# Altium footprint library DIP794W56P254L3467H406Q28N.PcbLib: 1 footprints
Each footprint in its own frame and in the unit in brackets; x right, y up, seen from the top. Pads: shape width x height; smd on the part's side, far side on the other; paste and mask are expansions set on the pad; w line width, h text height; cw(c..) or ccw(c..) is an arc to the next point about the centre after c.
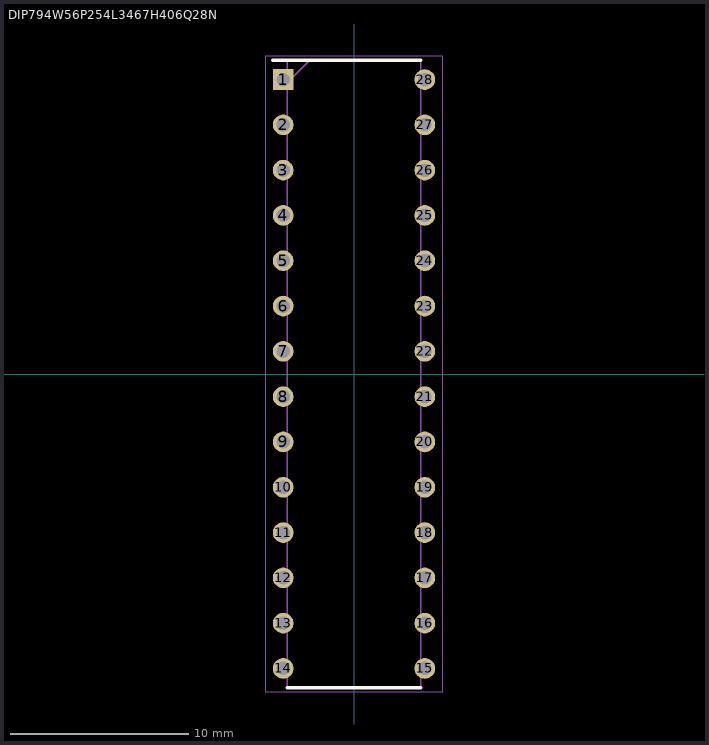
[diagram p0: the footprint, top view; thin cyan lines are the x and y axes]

## DIP794W56P254L3467H406Q28N [mm]
pads (28):
  rect 1.16x1.16 / inner round 1.16 / far side rect 1.16x1.16 hole 0.76: 1(-3.97,16.51)
  round 1.16 hole 0.76: 2(-3.97,13.97) 3(-3.97,11.43) 4(-3.97,8.89) 5(-3.97,6.35) 6(-3.97,3.81) 7(-3.97,1.27) 8(-3.97,-1.27) 9(-3.97,-3.81) 10(-3.97,-6.35) 11(-3.97,-8.89) 12(-3.97,-11.43) 13(-3.97,-13.97) 14(-3.97,-16.51) 15(3.97,-16.51) 16(3.97,-13.97) 17(3.97,-11.43) 18(3.97,-8.89) 19(3.97,-6.35) 20(3.97,-3.81) 21(3.97,-1.27) 22(3.97,1.27) 23(3.97,3.81) 24(3.97,6.35) 25(3.97,8.89) 26(3.97,11.43) 27(3.97,13.97) 28(3.97,16.51)
Top Overlay:
  lines w0.2: -4.55,17.59 3.745,17.59 ; -3.745,-17.59 3.745,-17.59
Mechanical 15:
  lines w0.1: -3.745,16.32 -2.475,17.59 ; -3.745,-17.59 3.745,-17.59 3.745,17.59 -3.745,17.59 -3.745,-17.59
Mechanical 20:
  lines w0.05: -4.96,-17.84 4.96,-17.84 4.96,17.84 -4.96,17.84 -4.96,-17.84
